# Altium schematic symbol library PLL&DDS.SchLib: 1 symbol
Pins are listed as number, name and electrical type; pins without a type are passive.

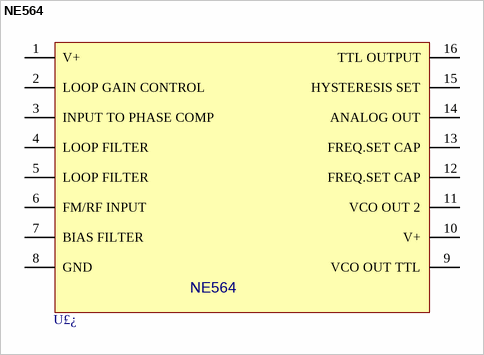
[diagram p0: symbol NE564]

## NE564
designator U£¿
Manufacturer: Philips; Class 1: PLL&DDS; Class 2: Phase Lock Loop
footprint DIP16
pins: 1 V+ (power), 2 LOOP GAIN CONTROL, 3 INPUT TO PHASE COMP, 4 LOOP FILTER, 5 LOOP FILTER, 6 FM/RF INPUT, 7 BIAS FILTER, 8 GND (power), 9 VCO OUT TTL, 10 V+, 11 VCO OUT 2, 12 FREQ.SET CAP, 13 FREQ.SET CAP, 14 ANALOG OUT, 15 HYSTERESIS SET, 16 TTL OUTPUT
